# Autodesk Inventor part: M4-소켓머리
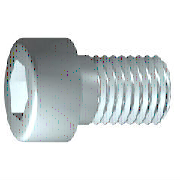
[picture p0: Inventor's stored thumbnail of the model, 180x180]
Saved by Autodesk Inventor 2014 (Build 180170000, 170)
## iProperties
IsCustomPart: 0
Company: 한국ATC센터
Created: 2014-08
Part Number: M4-소켓머리
Material: 강, 연강
Description: 6각머리 태핑 나사
Document SubType Name: Modeling
Standard: KS B 1003
Designer: KYOUNG IL JANG
Standards Organization: KS
Language: ko-KR
Size Designation: M 4 x 12
Categories: <MemberInstance><Categories><Category DisplayName="조임쇠" InternalName="e4da775c-781d-43d5-af7c-5136215cf5a6" Mnemonic="FSTN"><Category DisplayName="볼트" InternalN
Density: 7.86 g/cm^3
Checked By: KYOUNG IL JANG
Appearance: _시험-금속-강(연마)
Mass: 2.23465 g
Surface Area: 3.30853 cm^2
Volume: 0.284306 cm^3
Author: KYOUNG IL JANG
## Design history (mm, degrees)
sketch "스케치1"
  geometry: L1 (-1, 0)-(12, 0); L2 (12, 0)-(12, 2); L3 (12, 2)-(1.75, 2); L4 (1.75, 2)-(1.32, 2); L5 (1.32, 2)-(0, 2); L6 (0, 2)-(0, 3.5); L7 (0, 3.5)-(-4, 3.5); L8 (-4, 3.5)-(-4, 1.732); L9 (-4, 1.732)-(-2, 1.732); L10 (-2, 1.732)-(-1, 0); L11 (-7.2, 0)-(15.2, 0) reference; L12 (0, -0.7)-(0, 4.2) reference; L13 (1.75, 2)-(0, 2)
  constraints: 22 end point, 6 parallel, 2 collinear, 2 perpendicular, 1 horizontal, 1 point on line
  dimensions: "d1" = 10.25 distance from line of L3.end L2 (= GEL); "d2" = 0.42952 distance of L4.end L3.end (computed from GAL); "d3" = 4 distance between parallel lines of L8 L6 (= KOH); "d4" = 2 distance of L8.end L9.end (= INTI); "d5" = 60 deg angle of L10 L1; "d6" = 4 diameter of L3 L1 (= GD); "d7" = 4 diameter of L5 L1 (= BDM); "d8" = 3.4641 diameter of L9 L1 (= 1.1547 x SW); "d9" = 7 diameter of L7 L1 (= KOD); "d26" = 12 distance between parallel lines of L12 L2 (= NLG)
revolve "본체" sketch "스케치1" stored, may be unused: angle "d10" = 90 deg
sketch "스케치2"
  geometry: L1 (0, -4.9)-(0, 4.9) reference; L2 (-4.9, 0)-(4.9, 0) reference; L3 (1.732, 0)-(0.866, -1.5); L4 (0.866, -1.5)-(-0.866, -1.5); L5 (-0.866, -1.5)-(-1.732, 0); L6 (-1.732, 0)-(-0.866, 1.5); L7 (-0.866, 1.5)-(0.866, 1.5); L8 (0.866, 1.5)-(1.732, 0); 2 further points
  constraints: 12 end point, 1 coincident, 1 horizontal alignment, 1 point on line, 12 other
extrude "슬롯" join sketch "스케치2" stored distance "d11" = 10; taper "d12" = 0 deg
workplane "Work Plane1"
fillet "Fillet2" dims "d30" = 0.1 (= R)
body "Solid1"
fillet "모깎기1" dims "d17" = 0.4 (= RR)
feature "스레드" dims "d13" = 10.25 (= GEL), "d14" = 0
chamfer "모따기1" distance "d15" = 0.42941 (= -0.5 x SPD + 0.5 x GD); stored, may be unused: second distance "d16" = 0.42941 (= GUL), angle "d27" = 45 deg
other parameters: "GD" = 4 (= NND) [user parameter; used in 2 equation terms], "NLG" = 12 [user parameter; used in 1 equation term], "GEL" = 10.25 [user parameter; used in 2 equation terms], "KOD" = 7 [user parameter; used in 1 equation term], "KOH" = 4 [user parameter; used in 1 equation term], "INTI" = 2 [user parameter; used in 1 equation term], "GAL" = 0.42941 (= 0.61345 x PTC) [user parameter; used in 1 equation term], "GUL" = 0.42941 (= 0.61345 x PTC) [user parameter; used in 1 equation term], "BDM" = 4 (= NND) [user parameter; used in 1 equation term], "SW" = 3 [user parameter; used in 2 equation terms], "RR" = 0.4 [user parameter; used in 1 equation term], "SPD" = 3.14117 (= NND - 1.2269 x PTC) [user parameter; used in 1 equation term], "d19" = 0, "d28" = 0, "d29" = 0, "R" = 0.1 [user parameter; used in 1 equation term], "PHH" = 0.2 [user parameter], "GD1" = 3.14117 (= THREADDIA - 1.2269 x PTC) [user parameter], "THREADDIA" = 4 [user parameter; used in 1 equation term], "FAWI" = 45 deg [user parameter], "TPU" = 14.28571 (computed from PTC) [user parameter], "PTC" = 0.7 [user parameter; used in 5 equation terms], "NND" = 4 [user parameter; used in 3 equation terms], "TOA" = 30 deg [user parameter], "E0" = 3.465 (= 1.155 x SW) [user parameter]
